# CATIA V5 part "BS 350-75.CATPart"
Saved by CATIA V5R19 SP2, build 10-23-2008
Part number: BS 300-75
Bounding box of the stored display mesh (mm): x -15.868 to 15.868, y -15.868 to 15.868, z 0 to 180
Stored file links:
  C:\Users\Bora\Desktop\3D Katı model\BS serisi\BS 300\BS 300-75.CATPart
  C:\Program Files\Dassault Systemes\B19\intel_a\reffiles\standard\MetricThickPitch.txt
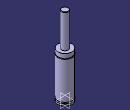
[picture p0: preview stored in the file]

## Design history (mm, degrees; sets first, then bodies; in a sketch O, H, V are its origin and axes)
Body1 (main body)
  Sketch1 on yz-plane, origin (0, 0, 0), H (0, 1, 0), V (0, 0, 1)
    point P1 (8, 179)
    point P3 (8, 179)
    point P5 (16, 94.5)
    point P6 (16, 92.5)
    point P9 (16, 94.5)
    point P14 (16, 92.5)
    line L1 (8, 179) -> (8, 104)
    arc A1 centre (7, 179) radius 1 from (8, 179) to (7, 180) ccw
    arc A2 centre (16, 93.5) radius 1 from (16, 94.5) to (16, 92.5) ccw
    line L2 (16, 0) -> (16, 4)
    line L3 (16, 94.5) -> (16, 104)
    line L4 (14.5, 7.5) -> (14.5, 4)
    line L5 (16, 7.5) -> (16, 92.5)
    line L6 (7, 180) -> (0, 180)
    point P15 (0, 180)
    line L7 (8, 104) -> (16, 104)
    line L8 (0, 0) -> (16, 0)
    line L9 (14.5, 7.5) -> (16, 7.5)
    line L10 (14.5, 4) -> (16, 4)
    coincidence: P15 V, P1 P3, P5 P9, P6 P14
    tangency: L6 A1
    horizontal: L7 H, L8 H, L9 H, L10 H
  Shaft1: profile Sketch1, axis Sketch1.V, angle 360
  Sketch2 on face of Shaft1 from Sketch1.L8, origin (0, 0, 0), H (1, 0, 0), V (0, -1, 0)
    point P1 (0, 0)
  Hole1: placed by Sketch2, at (0, 0, 0) direction (0, 0, 1), diameter 6.647, depth 4, threaded "M8", thread diameter 8, thread depth 4, pitch 1.25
